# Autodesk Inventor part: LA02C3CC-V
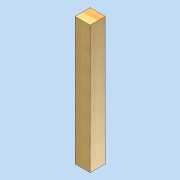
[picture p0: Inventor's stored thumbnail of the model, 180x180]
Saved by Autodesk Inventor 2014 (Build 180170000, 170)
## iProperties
Created: 2013-02
Part Number: LA02C3CC-V
Document SubType Name: Modeling
Designer: david.appleford
Density: 0.44 g/cm^3
Description: Lug Corner 0.5w 3 Slots
Cost Center: £6.00
Mass: 1169.87 g
Surface Area: 1656.48 cm^2
Volume: 2658.8 cm^3
Material: 000 Redwood
Appearance: Wood (Pine)
Justset: False
Author: david.appleford
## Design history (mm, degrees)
sketch "Sketch1"
  geometry: L1 (0, 0)-(68, 0); L2 (68, 0)-(68, 68); L3 (68, 68)-(0, 68); L4 (0, 68)-(0, 0)
  constraints: 8 end point, 2 parallel, 1 horizontal, 1 perpendicular
  dimensions: "d0" = 68 distance between parallel lines of L2 L4 (= t); "d1" = 68 distance between parallel lines of L1 L3 (= t)
extrude "Extrusion1" new body sketch "Sketch1" distance "d2" = 575 (= -0.5 x Cl + 0.5 x w - 0.5 x t); taper "d3" = 0 deg
body "Solid1"
other parameters: "t" = 68 [user parameter; used in 3 equation terms], "Cl" = 2 [user parameter; used in 1 equation term]
